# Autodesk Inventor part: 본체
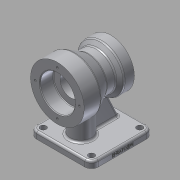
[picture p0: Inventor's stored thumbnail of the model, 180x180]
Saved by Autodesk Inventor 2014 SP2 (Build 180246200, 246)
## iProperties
Created: 2019-01
Part Number: 본체
Material: 알루미늄 6061
Document SubType Name: Modeling
Designer: CM-CAD
Density: 2.71 g/cm^3
Appearance: 알루미늄 - 평지
Mass: 902.144 g
Surface Area: 600.964 cm^2
Volume: 332.895 cm^3
Author: CM-CAD
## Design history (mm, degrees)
sketch "스케치1"
  geometry: L1 (-46, -46)-(46, -46); L2 (46, -46)-(46, 46); L3 (46, 46)-(-46, 46); L4 (-46, 46)-(-46, -46); L5 (-46, -46)-(46, 46); L6 (46, -46)-(-46, 46); 1 further point
  constraints: 12 end point, 2 midpoint, 2 parallel, 1 horizontal, 1 perpendicular
  dimensions: "d0" = 92 distance of L3.end L2.end; "d1" = 92 distance of L2.end L1.end
extrude "돌출1" new body sketch "스케치1" distance "d2" = 10; taper "d3" = 0 deg
sketch "스케치2"
  geometry: L1 (-46, -46)-(46, -46) reference; C1 r 16 at (0, -16); 1 further point
  constraints: 1 centre point
  dimensions: "d4" = 32 diameter of C1; "d5" = 30 distance from line of C1.centre L1
extrude "돌출2" join sketch "스케치2" distance "d6" = 70; taper "d7" = 0 deg
sketch "스케치3"
  geometry: L1 (0, 80)-(-32, 80) reference; L2 (-32, 10)-(-32, 80) reference; L3 (0, 10)-(0, 80) reference; L4 (46, 10)-(-46, 10) reference; L5 (-71.359, 80)-(65.608, 80); L6 (-51, 80)-(-51, 120); L7 (-51, 120)-(-26, 120); L8 (-26, 120)-(-5.215, 108); L9 (-5.215, 108)-(8.126, 108); L10 (8.126, 108)-(14, 115); L11 (14, 115)-(29, 115); L12 (29, 115)-(29, 80); L13 (-46, 0)-(-46, 10) reference; 1 further point
  constraints: 16 end point, 3 parallel, 3 perpendicular, 3 point on line, 1 collinear
  dimensions: "d8" = 80 diameter of L7 L5; "d9" = 5 distance between parallel lines of L6 L13; "d10" = 25 distance of L7.end L6.end; "d11" = 80 distance between parallel lines of L6 L12; "d12" = 15 distance from line of L10.end L12; "d13" = 56 diameter of L9 L5; "d14" = 30 deg angle of L8 L9; "d15" = 50 deg angle of L10 L9; "d16" = 70 diameter of L11 L5
revolve "회전1" sketch "스케치3" stored, may be unused: angle "d17" = 90 deg
sketch "스케치4"
  geometry: L1 (46, 10)-(-46, 10) reference; L2 (46, 0)-(46, 10) reference; L3 (14, 45)-(29, 45) reference; L4 (8.126, 52)-(14, 45) reference; L5 (0, 52)-(8.126, 52) reference; L6 (36, 10)-(10.93, 63.764); 1 further point
  constraints: 2 end point, 1 point on line
  dimensions: "d18" = 10 distance of L1.start L6.start; "d19" = 25 deg angle of L6 L2
feature "리브1" sketch "스케치4" dims "d20" = 1, "d21" = 10, "d22" = 0, "d23" = 0, "d24" = 1, "d25" = 1
fillet "모깎기1" dims "d26" = 10
hole "구멍1" diameter "d29" = 52; stored, may be unused: countersink angle "d33" = 90 deg, drill point angle "d35" = 0 deg; dims "d27" = 10, "d28" = 10, "d30" = 6, "d31" = 4, "d32" = 2, "d34" = 20
hole "구멍2" diameter "d38" = 32; stored, may be unused: countersink angle "d42" = 90 deg, drill point angle "d44" = 0 deg; dims "d39" = 6, "d40" = 4, "d41" = 2, "d43" = 43, "d45" = 10, "d46" = 10
hole "구멍3" diameter "d49" = 40; stored, may be unused: countersink angle "d53" = 90 deg, drill point angle "d55" = 0 deg; dims "d47" = 10, "d48" = 10, "d50" = 6, "d51" = 4, "d52" = 2, "d54" = 17
sketch "스케치5"
  geometry: C1 r 26 at (0, 0) reference; 2 further points
  dimensions: "d56" = 33 distance of point (0, 33) C1.centre
hole "구멍4" sketch "스케치5" at (0, 33) diameter "d57" = 3.242; stored, may be unused: countersink angle "d61" = 90 deg, drill point angle "d63" = 118 deg; dims "d58" = 9, "d59" = 4, "d60" = 2, "d62" = 11
sketch "스케치6"
  geometry: C1 r 20 at (0, 0) reference; 2 further points
  dimensions: "d67" = 27.5 distance of point (0, -27.5) C1.centre
hole "구멍5" sketch "스케치6" at (0, -27.5) diameter "d68" = 3.242; stored, may be unused: countersink angle "d72" = 90 deg, drill point angle "d74" = 118 deg; dims "d69" = 9, "d70" = 4, "d71" = 2, "d73" = 11
sketch "스케치7"
  geometry: A1 r 10 centre (-36, 36) between (-36, 46) and (-46, 36) reference; A2 r 10 centre (36, 36) between (46, 36) and (36, 46) reference; 3 further points
  constraints: 2 coincident
hole "구멍6" sketch "스케치7" at (-36, 36), (36, 36) diameter "d78" = 9; stored, may be unused: countersink angle "d82" = 90 deg, drill point angle "d84" = 0 deg; dims "d79" = 9, "d80" = 4, "d81" = 2, "d83" = 11
fillet "모깎기2" dims "d85" = 1
fillet "모깎기3" dims "d86" = 0.6
fillet "모깎기4" dims "d87" = 3
fillet "모깎기5" dims "d88" = 3
fillet "모깎기6" dims "d89" = 3
chamfer "모따기1" distance "d90" = 1; stored, may be unused: second distance "d91" = 2, angle "d92" = 45 deg
sketch "스케치8"
  geometry: L1 (-4.447, 19.686)-(-4.447, 52.87); L2 (-4.447, 52.87)-(-4.038, 52.87); L3 (-4.038, 52.87)-(-4.038, 19.686); L4 (-4.038, 19.686)-(-4.447, 19.686); 1 further point
  constraints: 2 other
feature "엠보싱1" sketch "스케치8" dims "d0" = 92, "d1" = 92, "d93" = 0.5, "d94" = 0
node "솔리드1"
pattern_circular "원형 패턴1" dims angle "d65" = 360 deg
pattern_circular "원형 패턴2" dims angle "d76" = 360 deg
mirror "대칭1"
